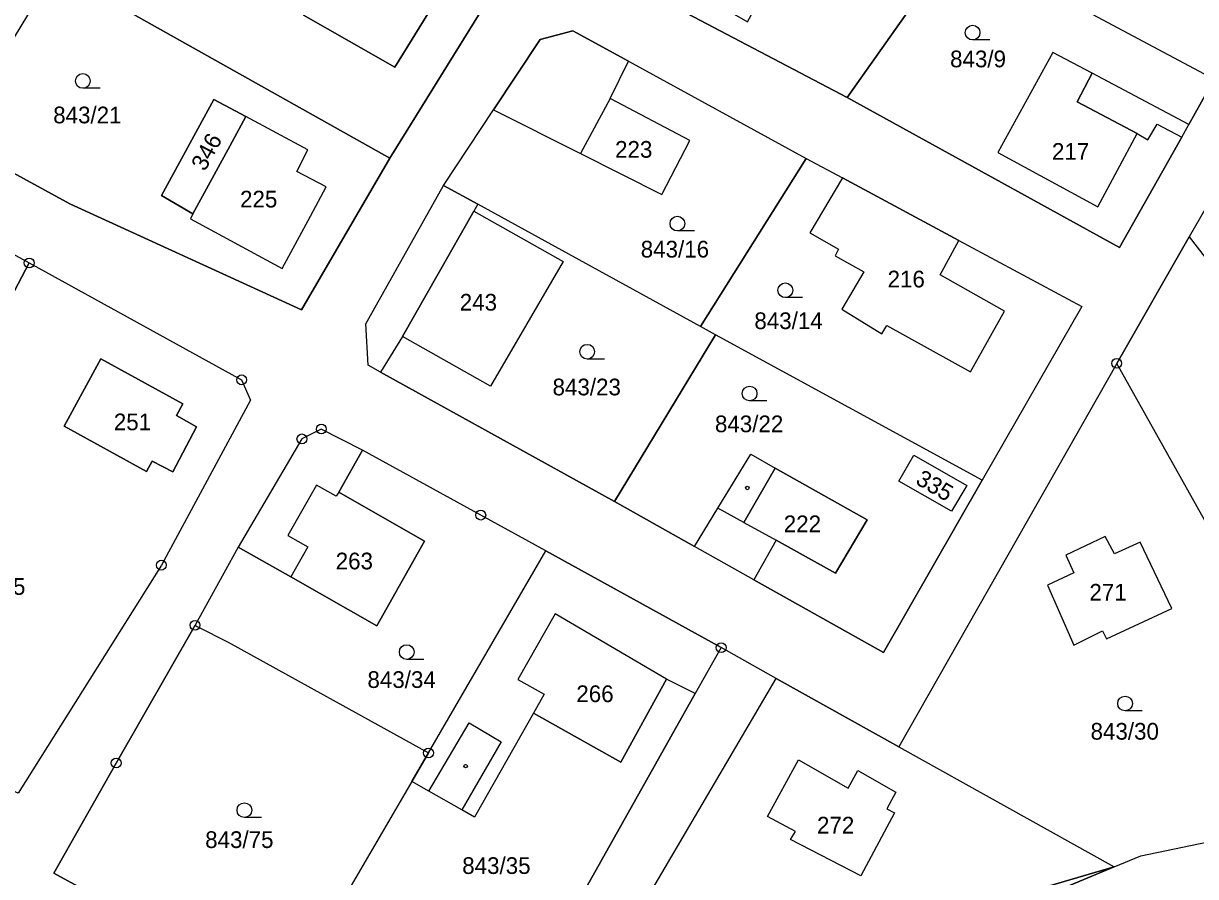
# Model space of a CAD drawing. Extents: x -654083 to -650132, y -1099819 to -1096699.
# Drawn here: x -652451.7 to -652332.5, y -1098329.1 to -1098242.3 of the extents above; entities that cross this region are included whole.
import ezdxf

# ---------------------------------------------------------------- set-up
doc = ezdxf.new("R2010")
doc.units = 0
for name, color, linetype in [('Geodetické body', 7, 'Continuous'), ('Hranice - vnitř_ kresba', 7, 'Continuous'), ('Obvody jako plochy', 7, 'Continuous'), ('Parcelní čísla', 7, 'Continuous'), ('Značky kultur', 7, 'Continuous'), ('Značky na budově ne v SPI', 7, 'Continuous')]:
    doc.layers.add(name, color=color, linetype=linetype)

msp = doc.modelspace()

# ---------------------------------------------------------------- linework, layer by layer
at = {"layer": 'Geodetické body'}
for centre, radius in [((-652451.14, -1098266.7), 0.5), ((-652451.14, -1098266.7), 0.001), ((-652340.51, -1098276.92), 0.5), ((-652340.51, -1098276.92), 0.001), ((-652429.53, -1098278.59), 0.5), ((-652429.53, -1098278.59), 0.001), ((-652423.4, -1098284.6), 0.5), ((-652421.43, -1098283.6), 0.5), ((-652421.43, -1098283.6), 0.001), ((-652423.4, -1098284.6), 0.001), ((-652405.2, -1098292.35), 0.5), ((-652405.2, -1098292.35), 0.001), ((-652437.69, -1098297.44), 0.5), ((-652437.69, -1098297.44), 0.001), ((-652434.27, -1098303.56), 0.5), ((-652434.27, -1098303.56), 0.001), ((-652380.75, -1098305.83), 0.5), ((-652380.75, -1098305.83), 0.001), ((-652410.52, -1098316.54), 0.5), ((-652442.29, -1098317.57), 0.5), ((-652410.52, -1098316.54), 0.001), ((-652442.29, -1098317.57), 0.001)]:
    msp.add_circle(centre, radius, dxfattribs=at)
at = {"layer": 'Hranice - vnitř_ kresba'}
for p, q in [((-652343.01, -1098247.41), (-652344.52, -1098250.33)), ((-652392.04, -1098249.96), (-652395.07, -1098255.57)), ((-652344.52, -1098250.33), (-652338.42, -1098253.53)), ((-652405.9, -1098261.44), (-652413.16, -1098274.18)), ((-652378.43, -1098293.09), (-652375.24, -1098287.58)), ((-652421.91, -1098289.3), (-652424.82, -1098294.42)), ((-652419.9, -1098290.44), (-652421.91, -1098289.3)), ((-652419.65, -1098290), (-652419.9, -1098290.44)), ((-652378.43, -1098293.09), (-652381.07, -1098291.65)), ((-652378.43, -1098293.09), (-652375.15, -1098294.91)), ((-652424.82, -1098294.42), (-652422.8, -1098295.57)), ((-652422.8, -1098295.57), (-652424.53, -1098298.63)), ((-652397.63, -1098302.38), (-652401.42, -1098309.07)), ((-652386.31, -1098309.03), (-652397.63, -1098302.38)), ((-652401.42, -1098309.07), (-652398.77, -1098310.58)), ((-652398.77, -1098310.58), (-652399.83, -1098312.49)), ((-652410.49, -1098320.42), (-652406.38, -1098313.48)), ((-652406.38, -1098313.48), (-652403.14, -1098315.4)), ((-652403.14, -1098315.4), (-652407.14, -1098322.34))]:
    msp.add_line(p, q, dxfattribs=at)
at = {"layer": 'Obvody jako plochy'}
for points in [[(-652412.58, -1098234.48), (-652404.85, -1098238.65), (-652405.26, -1098241.23), (-652414.45, -1098256.06), (-652423.45, -1098271.48), (-652447.01, -1098260.7), (-652459, -1098254.16), (-652470.33, -1098247.92), (-652493.88, -1098235.58), (-652514.5, -1098224.43), (-652515.09, -1098221.42), (-652505.66, -1098206.07), (-652494.88, -1098190.13), (-652481.36, -1098197.42), (-652478.97, -1098198.71), (-652464.63, -1098206.44), (-652437.63, -1098220.99), (-652433.22, -1098223.36), (-652419.95, -1098230.51)], [(-652334.34, -1098234.45), (-652335.39, -1098236.5), (-652352.08, -1098227.18), (-652356.55, -1098233.74), (-652344.54, -1098240.59), (-652330.58, -1098248.02), (-652319.01, -1098231.53), (-652326.79, -1098224.22), (-652332.9, -1098220.29), (-652335.69, -1098226.19), (-652331.24, -1098228.54)], [(-652356.55, -1098233.74), (-652367.94, -1098249.87), (-652391.05, -1098237.69), (-652389.72, -1098235.46), (-652378.07, -1098242.16), (-652374.95, -1098236.45), (-652380.2, -1098233.41), (-652378.65, -1098230.46), (-652383.43, -1098227.91), (-652379.94, -1098221.28)], [(-652423.22, -1098241.49), (-652422.84, -1098240.83), (-652425.02, -1098239.65), (-652419.95, -1098230.51), (-652433.22, -1098223.36), (-652442.8, -1098240.15), (-652414.45, -1098256.06), (-652405.26, -1098241.23), (-652404.85, -1098238.65), (-652412.58, -1098234.48), (-652414.52, -1098238.06), (-652410.14, -1098240.64), (-652413.93, -1098246.8)], [(-652452.25, -1098320.64), (-652453.03, -1098320.31), (-652482.82, -1098329.7), (-652501.09, -1098319.77), (-652519.51, -1098309.76), (-652538.73, -1098299.32), (-652557.1, -1098289.51), (-652558.61, -1098285.27), (-652541.02, -1098258.51), (-652531.03, -1098243.32), (-652521.22, -1098228.39), (-652504.75, -1098237.38), (-652495.89, -1098242.22), (-652468.6, -1098257.11), (-652451.14, -1098266.7), (-652429.53, -1098278.59), (-652428.62, -1098280.65), (-652437.69, -1098297.44)], [(-652425.02, -1098239.65), (-652422.84, -1098240.83), (-652423.22, -1098241.49), (-652413.93, -1098246.8), (-652410.14, -1098240.64), (-652414.52, -1098238.06), (-652412.58, -1098234.48), (-652419.95, -1098230.51)], [(-652337.33, -1098254.19), (-652336.39, -1098252.59), (-652333.9, -1098253.91), (-652340.23, -1098265.14), (-652367.94, -1098249.87), (-652356.55, -1098233.74), (-652344.54, -1098240.59), (-652330.58, -1098248.02), (-652333.17, -1098252.61), (-652343.01, -1098247.41), (-652347.02, -1098245.29), (-652352.6, -1098255.46), (-652342.44, -1098260.99), (-652338.42, -1098253.53)], [(-652413.93, -1098246.8), (-652423.22, -1098241.49), (-652422.84, -1098240.83), (-652419.54, -1098235.1), (-652414.52, -1098238.06), (-652410.14, -1098240.64)], [(-652414.45, -1098256.06), (-652442.8, -1098240.15), (-652448.5, -1098236.83), (-652459, -1098254.16), (-652447.01, -1098260.7), (-652423.45, -1098271.48)], [(-652321.81, -1098268.67), (-652318.81, -1098266.32), (-652315.52, -1098263.73), (-652308.44, -1098258.18), (-652310.27, -1098255.8), (-652309.22, -1098253.23), (-652310.87, -1098251), (-652313.5, -1098251.55), (-652316.79, -1098247.24), (-652319.82, -1098249.62), (-652322.73, -1098245.89), (-652315.59, -1098236.82), (-652300.55, -1098258.22), (-652310.58, -1098270.64), (-652331.06, -1098293.74), (-652340.51, -1098276.92), (-652333.13, -1098264.04), (-652326.64, -1098272.46)], [(-652403.9, -1098251.14), (-652399.16, -1098243.97), (-652395.85, -1098243.08), (-652390.16, -1098246.19), (-652372.1, -1098256.08), (-652368.42, -1098258.05), (-652356.56, -1098264.42), (-652344.07, -1098271.13), (-652354.19, -1098288.81), (-652364.22, -1098306.33), (-652377.43, -1098298.92), (-652383.45, -1098295.55), (-652391.6, -1098290.98), (-652415.41, -1098277.8), (-652416.65, -1098277.11), (-652416.88, -1098272.89), (-652408.98, -1098258.81)], [(-652392.04, -1098249.96), (-652390.16, -1098246.19), (-652395.85, -1098243.08), (-652399.16, -1098243.97), (-652403.9, -1098251.14), (-652395.07, -1098255.57), (-652386.77, -1098259.73), (-652383.93, -1098254.26)], [(-652338.42, -1098253.53), (-652337.33, -1098254.19), (-652336.39, -1098252.59), (-652333.9, -1098253.91), (-652333.17, -1098252.61), (-652343.01, -1098247.41), (-652347.02, -1098245.29), (-652352.6, -1098255.46), (-652342.44, -1098260.99)], [(-652343.01, -1098247.41), (-652347.02, -1098245.29), (-652352.6, -1098255.46), (-652342.44, -1098260.99), (-652338.42, -1098253.53), (-652344.52, -1098250.33)], [(-652308.44, -1098258.18), (-652310.27, -1098255.8), (-652309.22, -1098253.23), (-652310.87, -1098251), (-652313.5, -1098251.55), (-652316.79, -1098247.24), (-652319.82, -1098249.62), (-652322.73, -1098245.89), (-652329.05, -1098256.91), (-652333.13, -1098264.04), (-652326.64, -1098272.46), (-652321.81, -1098268.67), (-652318.81, -1098266.32), (-652315.52, -1098263.73)], [(-652326.64, -1098272.46), (-652321.81, -1098268.67), (-652327.1, -1098261.88), (-652324.13, -1098259.48), (-652318.81, -1098266.32), (-652315.52, -1098263.73), (-652308.44, -1098258.18), (-652310.27, -1098255.8), (-652309.22, -1098253.23), (-652310.87, -1098251), (-652313.5, -1098251.55), (-652316.79, -1098247.24), (-652319.82, -1098249.62), (-652322.73, -1098245.89), (-652329.05, -1098256.91), (-652333.13, -1098264.04)], [(-652372.1, -1098256.08), (-652382.84, -1098273.17), (-652405.49, -1098260.73), (-652408.98, -1098258.81), (-652403.9, -1098251.14), (-652395.07, -1098255.57), (-652386.77, -1098259.73), (-652383.93, -1098254.26), (-652392.04, -1098249.96), (-652390.16, -1098246.19)], [(-652422.52, -1098261.95), (-652420.94, -1098258.96), (-652423.9, -1098257.39), (-652422.8, -1098255.21), (-652429.09, -1098251.82), (-652432.36, -1098250.06), (-652437.69, -1098259.83), (-652434.48, -1098261.71), (-652434.74, -1098262.21), (-652425.42, -1098267.26)], [(-652429.09, -1098251.82), (-652432.36, -1098250.06), (-652437.69, -1098259.83), (-652434.48, -1098261.71), (-652430.73, -1098254.82)], [(-652430.73, -1098254.82), (-652434.48, -1098261.71), (-652437.69, -1098259.83), (-652432.36, -1098250.06), (-652429.09, -1098251.82)], [(-652386.77, -1098259.73), (-652383.93, -1098254.26), (-652392.04, -1098249.96), (-652395.07, -1098255.57)], [(-652430.73, -1098254.82), (-652434.48, -1098261.71), (-652434.74, -1098262.21), (-652425.42, -1098267.26), (-652422.52, -1098261.95), (-652420.94, -1098258.96), (-652423.9, -1098257.39), (-652422.8, -1098255.21), (-652429.09, -1098251.82)], [(-652434.74, -1098262.21), (-652425.42, -1098267.26), (-652422.52, -1098261.95), (-652420.94, -1098258.96), (-652423.9, -1098257.39), (-652422.8, -1098255.21), (-652429.09, -1098251.82), (-652430.73, -1098254.82), (-652434.48, -1098261.71)], [(-652351.94, -1098271.62), (-652358.47, -1098267.92), (-652356.56, -1098264.42), (-652344.07, -1098271.13), (-652354.19, -1098288.81), (-652381.32, -1098274), (-652382.84, -1098273.17), (-652372.1, -1098256.08), (-652368.42, -1098258.05), (-652371.74, -1098263.63), (-652368.82, -1098265.29), (-652369.16, -1098265.98), (-652366.24, -1098267.59), (-652368.47, -1098271.39), (-652364.41, -1098273.91), (-652363.9, -1098273.05), (-652355.4, -1098277.79)], [(-652468.6, -1098257.11), (-652451.14, -1098266.7), (-652457.21, -1098278.22), (-652461.18, -1098275.97), (-652469.47, -1098271.27), (-652474.5, -1098268.42)], [(-652405.9, -1098261.44), (-652396.81, -1098266.54), (-652404.21, -1098279.22), (-652413.16, -1098274.18), (-652415.41, -1098277.8), (-652416.65, -1098277.11), (-652416.88, -1098272.89), (-652408.98, -1098258.81), (-652405.49, -1098260.73)], [(-652368.82, -1098265.29), (-652369.16, -1098265.98), (-652366.24, -1098267.59), (-652368.47, -1098271.39), (-652364.41, -1098273.91), (-652363.9, -1098273.05), (-652355.4, -1098277.79), (-652351.94, -1098271.62), (-652358.47, -1098267.92), (-652356.56, -1098264.42), (-652368.42, -1098258.05), (-652371.74, -1098263.63)], [(-652368.42, -1098258.05), (-652371.74, -1098263.63), (-652368.82, -1098265.29), (-652369.16, -1098265.98), (-652366.24, -1098267.59), (-652368.47, -1098271.39), (-652364.41, -1098273.91), (-652363.9, -1098273.05), (-652355.4, -1098277.79), (-652351.94, -1098271.62), (-652358.47, -1098267.92), (-652356.56, -1098264.42)], [(-652391.6, -1098290.98), (-652381.32, -1098274), (-652382.84, -1098273.17), (-652405.49, -1098260.73), (-652405.9, -1098261.44), (-652396.81, -1098266.54), (-652404.21, -1098279.22), (-652413.16, -1098274.18), (-652415.41, -1098277.8)], [(-652404.21, -1098279.22), (-652413.16, -1098274.18), (-652405.9, -1098261.44), (-652396.81, -1098266.54)], [(-652428.62, -1098280.65), (-652437.69, -1098297.44), (-652452.25, -1098320.64), (-652453.03, -1098320.31), (-652466.48, -1098314.63), (-652474.83, -1098311.1), (-652467.26, -1098297.29), (-652460.45, -1098284.37), (-652457.21, -1098278.22), (-652451.14, -1098266.7), (-652429.53, -1098278.59)], [(-652375.15, -1098294.91), (-652377.43, -1098298.92), (-652364.22, -1098306.33), (-652354.19, -1098288.81), (-652381.32, -1098274), (-652391.6, -1098290.98), (-652383.45, -1098295.55), (-652381.07, -1098291.65), (-652377.74, -1098286.16), (-652375.24, -1098287.58), (-652365.88, -1098292.83), (-652369.1, -1098298.26)], [(-652436.54, -1098287.96), (-652434.11, -1098283.36), (-652436.14, -1098282.21), (-652435.51, -1098281.04), (-652443.85, -1098276.45), (-652447.58, -1098283.31), (-652439.2, -1098287.93), (-652438.63, -1098286.87)], [(-652438.63, -1098286.87), (-652439.2, -1098287.93), (-652447.58, -1098283.31), (-652443.85, -1098276.45), (-652435.51, -1098281.04), (-652436.14, -1098282.21), (-652434.11, -1098283.36), (-652436.54, -1098287.96)], [(-652436.54, -1098287.96), (-652434.11, -1098283.36), (-652436.14, -1098282.21), (-652435.51, -1098281.04), (-652443.85, -1098276.45), (-652447.58, -1098283.31), (-652439.2, -1098287.93), (-652438.63, -1098286.87)], [(-652313.3, -1098325.37), (-652323.04, -1098308.85), (-652331.06, -1098293.74), (-652340.51, -1098276.92), (-652362.69, -1098315.92), (-652340.76, -1098328.13), (-652338.05, -1098327), (-652330.4, -1098325.42), (-652327.75, -1098326.79)], [(-652421.43, -1098283.6), (-652423.4, -1098284.6), (-652429.88, -1098295.61), (-652424.53, -1098298.63), (-652415.77, -1098303.61), (-652410.91, -1098295), (-652419.65, -1098290), (-652417.24, -1098285.75)], [(-652410.52, -1098316.54), (-652398.57, -1098296), (-652405.2, -1098292.35), (-652417.24, -1098285.75), (-652419.65, -1098290), (-652410.91, -1098295), (-652415.77, -1098303.61), (-652424.53, -1098298.63), (-652429.88, -1098295.61), (-652434.27, -1098303.56), (-652434.06, -1098303.67), (-652430.89, -1098305.26)], [(-652377.43, -1098298.92), (-652383.45, -1098295.55), (-652381.07, -1098291.65), (-652377.74, -1098286.16), (-652375.24, -1098287.58), (-652365.88, -1098292.83), (-652369.1, -1098298.26), (-652375.15, -1098294.91)], [(-652361.16, -1098286.24), (-652355.77, -1098289.35), (-652357.31, -1098291.96), (-652362.68, -1098288.89)], [(-652355.77, -1098289.35), (-652357.31, -1098291.96), (-652362.68, -1098288.89), (-652361.16, -1098286.24)], [(-652355.77, -1098289.35), (-652357.31, -1098291.96), (-652362.68, -1098288.89), (-652361.16, -1098286.24)], [(-652365.88, -1098292.83), (-652375.24, -1098287.58), (-652378.43, -1098293.09), (-652375.15, -1098294.91), (-652369.1, -1098298.26)], [(-652424.82, -1098294.42), (-652422.8, -1098295.57), (-652424.53, -1098298.63), (-652415.77, -1098303.61), (-652410.91, -1098295), (-652419.65, -1098290), (-652419.9, -1098290.44), (-652421.91, -1098289.3)], [(-652338.12, -1098295.1), (-652340.72, -1098296.28), (-652341.67, -1098294.52), (-652345.7, -1098296.41), (-652344.87, -1098298.23), (-652347.56, -1098299.49), (-652344.86, -1098305.58), (-652341.94, -1098304.12), (-652341.56, -1098304.94), (-652334.89, -1098301.86)], [(-652341.67, -1098294.52), (-652345.7, -1098296.41), (-652344.87, -1098298.23), (-652347.56, -1098299.49), (-652344.86, -1098305.58), (-652341.94, -1098304.12), (-652341.56, -1098304.94), (-652334.89, -1098301.86), (-652338.12, -1098295.1), (-652340.72, -1098296.28)], [(-652341.94, -1098304.12), (-652341.56, -1098304.94), (-652334.89, -1098301.86), (-652338.12, -1098295.1), (-652340.72, -1098296.28), (-652341.67, -1098294.52), (-652345.7, -1098296.41), (-652344.87, -1098298.23), (-652347.56, -1098299.49), (-652344.86, -1098305.58)], [(-652412.21, -1098319.43), (-652410.52, -1098316.54), (-652398.57, -1098296), (-652380.75, -1098305.83), (-652383.38, -1098310.49), (-652386.31, -1098309.03), (-652390.96, -1098317.48), (-652399.83, -1098312.49), (-652405.83, -1098323.09), (-652407.14, -1098322.34), (-652410.49, -1098320.42)], [(-652386.31, -1098309.03), (-652397.63, -1098302.38), (-652401.42, -1098309.07), (-652398.77, -1098310.58), (-652399.83, -1098312.49), (-652390.96, -1098317.48)], [(-652434.06, -1098303.67), (-652430.89, -1098305.26), (-652410.52, -1098316.54), (-652412.21, -1098319.43), (-652418.64, -1098330.44), (-652425.17, -1098341.63), (-652448.63, -1098328.76), (-652442.29, -1098317.57), (-652434.27, -1098303.56)], [(-652380.75, -1098305.83), (-652383.38, -1098310.49), (-652400.43, -1098340.8), (-652418.64, -1098330.44), (-652425.17, -1098341.63), (-652397.28, -1098346.66), (-652395.89, -1098344.3), (-652375.14, -1098308.96)], [(-652383.38, -1098310.49), (-652386.31, -1098309.03), (-652390.96, -1098317.48), (-652399.83, -1098312.49), (-652405.83, -1098323.09), (-652407.14, -1098322.34), (-652410.49, -1098320.42), (-652412.21, -1098319.43), (-652418.64, -1098330.44), (-652400.43, -1098340.8)], [(-652362.69, -1098315.92), (-652340.76, -1098328.13), (-652395.89, -1098344.3), (-652375.14, -1098308.96)], [(-652372.88, -1098317.25), (-652367.84, -1098320.13), (-652366.83, -1098318.34), (-652362.99, -1098320.54), (-652363.89, -1098322.21), (-652363.11, -1098322.64), (-652366.55, -1098329.05), (-652373.69, -1098325.35), (-652373.19, -1098324.54), (-652376.05, -1098323)], [(-652363.11, -1098322.64), (-652366.55, -1098329.05), (-652373.69, -1098325.35), (-652373.19, -1098324.54), (-652376.05, -1098323), (-652372.88, -1098317.25), (-652367.84, -1098320.13), (-652366.83, -1098318.34), (-652362.99, -1098320.54), (-652363.89, -1098322.21)], [(-652373.69, -1098325.35), (-652373.19, -1098324.54), (-652376.05, -1098323), (-652372.88, -1098317.25), (-652367.84, -1098320.13), (-652366.83, -1098318.34), (-652362.99, -1098320.54), (-652363.89, -1098322.21), (-652363.11, -1098322.64), (-652366.55, -1098329.05)], [(-652338.05, -1098327), (-652330.4, -1098325.42), (-652327.75, -1098326.79), (-652313.3, -1098325.37), (-652311.1, -1098329.18), (-652326.52, -1098336.41), (-652329.39, -1098329.93), (-652391.55, -1098354.62), (-652381.5, -1098366.27), (-652399.95, -1098365.36), (-652478.52, -1098362.63), (-652531.67, -1098372.21), (-652535.49, -1098366.17), (-652545.7, -1098345.51), (-652546.92, -1098343), (-652518.45, -1098354.28), (-652508.1, -1098348.73), (-652482.03, -1098339.62), (-652463.05, -1098328.79), (-652450.84, -1098332.97), (-652422.5, -1098351.89), (-652404.15, -1098351.55), (-652393.84, -1098350.3), (-652340.76, -1098328.13)]]:
    msp.add_lwpolyline(points, close=True, dxfattribs=at)
for points in [[(-652460.54, -1098200.94), (-652447.46, -1098207.53), (-652442.8, -1098210.03), (-652429.64, -1098216.72), (-652402.23, -1098232.27), (-652399.99, -1098232.38), (-652394.75, -1098224.71), (-652391.68, -1098220.21), (-652389.03, -1098216.33), (-652375.51, -1098197.37), (-652369.91, -1098200.28), (-652383.29, -1098219.5), (-652393.66, -1098234.4), (-652393.64, -1098236.21), (-652391.05, -1098237.69), (-652367.94, -1098249.87), (-652340.23, -1098265.14), (-652333.9, -1098253.91), (-652333.17, -1098252.61), (-652330.58, -1098248.02)], [(-652329.05, -1098256.91), (-652333.13, -1098264.04), (-652340.51, -1098276.92), (-652362.69, -1098315.92), (-652375.14, -1098308.96), (-652380.75, -1098305.83), (-652398.57, -1098296), (-652405.2, -1098292.35), (-652417.24, -1098285.75), (-652421.43, -1098283.6), (-652423.4, -1098284.6), (-652429.88, -1098295.61), (-652434.27, -1098303.56), (-652442.29, -1098317.57), (-652448.63, -1098328.76), (-652425.17, -1098341.63)], [(-652395.89, -1098344.3), (-652340.76, -1098328.13), (-652393.84, -1098350.3)]]:
    msp.add_lwpolyline(points, dxfattribs=at)
at = {"layer": 'Značky kultur'}
for p, q in [((-652353.42, -1098244.02), (-652355.17, -1098244.02)), ((-652443.93, -1098248.94), (-652445.68, -1098248.94)), ((-652383.45, -1098263.45), (-652385.2, -1098263.45)), ((-652372.47, -1098270.23), (-652374.22, -1098270.23)), ((-652392.63, -1098276.48), (-652394.38, -1098276.48)), ((-652376.11, -1098280.73), (-652377.86, -1098280.73)), ((-652410.98, -1098307.03), (-652412.73, -1098307.03)), ((-652337.91, -1098312.26), (-652339.66, -1098312.26)), ((-652427.5, -1098323.11), (-652429.25, -1098323.11))]:
    msp.add_line(p, q, dxfattribs=at)
for centre in [(-652355.17, -1098243.27), (-652445.68, -1098248.19), (-652385.2, -1098262.7), (-652374.22, -1098269.48), (-652394.38, -1098275.73), (-652377.86, -1098279.98), (-652412.73, -1098306.28), (-652339.66, -1098311.51), (-652429.25, -1098322.36)]:
    msp.add_circle(centre, 0.75, dxfattribs=at)
at = {"layer": 'Značky na budově ne v SPI'}
for centre in [(-652378.09, -1098289.59), (-652406.74, -1098317.88)]:
    msp.add_circle(centre, 0.175, dxfattribs=at)

# ---------------------------------------------------------------- texts
at = {"layer": 'Parcelní čísla'}
for s, p in [('843/9', (-652357.46, -1098246.8)), ('843/21', (-652448.7, -1098252.5)), ('223', (-652391.54, -1098256)), ('217', (-652347.1, -1098256.21)), ('225', (-652429.69, -1098261.06)), ('843/16', (-652388.93, -1098266.15)), ('216', (-652363.82, -1098269.19)), ('243', (-652407.34, -1098271.55)), ('843/14', (-652377.37, -1098273.43)), ('843/23', (-652397.9, -1098280.17)), ('251', (-652442.53, -1098283.72)), ('843/22', (-652381.38, -1098283.92)), ('222', (-652374.38, -1098294.09)), ('263', (-652419.96, -1098297.87)), ('843/25', (-652458.48, -1098300.46)), ('271', (-652343.29, -1098301.05)), ('843/34', (-652416.73, -1098309.93)), ('266', (-652395.48, -1098311.37)), ('843/30', (-652343.17, -1098315.19)), ('272', (-652371, -1098324.74)), ('843/75', (-652433.24, -1098326.21)), ('843/35', (-652407.09, -1098328.85))]:
    msp.add_text(s, height=1.7, dxfattribs=at).set_placement(p)
for s, rotation, p in [('346', 61.605, (-652433.26, -1098257.46)), ('335', 329.724, (-652361.08, -1098289.11))]:
    msp.add_text(s, height=1.7, rotation=rotation, dxfattribs=at).set_placement(p)

doc.saveas('drawing.dxf')
